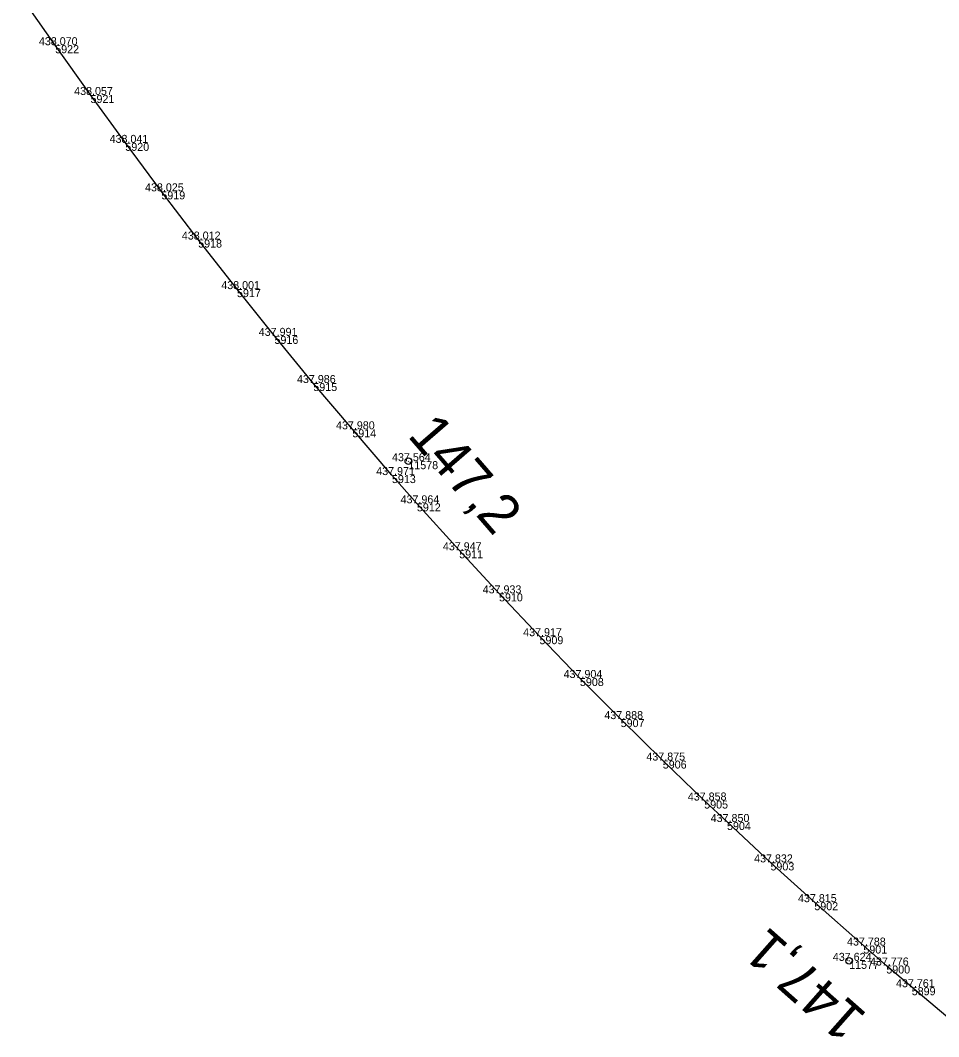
# Model space of a CAD drawing. Extents: x -654154 to -652650, y -1166925 to -1164904.
# Drawn here: x -653784.1 to -653646.5, y -1165513.2 to -1165360.8 of the extents above; entities that cross this region are included whole.
import ezdxf

# ---------------------------------------------------------------- set-up
doc = ezdxf.new("R2010")
doc.units = 0
for name, color, linetype in [('Vrstva 1', 7, 'Continuous'), ('Vrstva 60', 7, 'Continuous'), ('Vrstva 61', 7, 'Continuous'), ('Vrstva 7', 7, 'Continuous')]:
    doc.layers.add(name, color=color, linetype=linetype)

msp = doc.modelspace()

# ---------------------------------------------------------------- linework, layer by layer
at = {"layer": 'Vrstva 1'}
msp.add_lwpolyline([(-653643.5, -1165511.7), (-653650.49, -1165505.82), (-653654.3, -1165502.56), (-653657.74, -1165499.57), (-653665.09, -1165493.06), (-653671.67, -1165487.1), (-653678.18, -1165481.04), (-653681.6, -1165477.82), (-653687.81, -1165471.83), (-653694.12, -1165465.61), (-653700.23, -1165459.45), (-653706.29, -1165453.18), (-653712.36, -1165446.76), (-653718.33, -1165440.3), (-653724.67, -1165433.26), (-653728.41, -1165429.02), (-653734.35, -1165422.16), (-653740.2, -1165415.22), (-653746.02, -1165408.15), (-653751.64, -1165401.14), (-653757.46, -1165393.71), (-653762.98, -1165386.48), (-653768.38, -1165379.21), (-653773.6, -1165372.03), (-653778.89, -1165364.57), (-653784.12, -1165357.1)], dxfattribs=at)
at = {"layer": 'Vrstva 60'}
for p, q in [((-653778.89, -1165364.57), (-653778.89, -1165364.57)), ((-653773.6, -1165372.03), (-653773.6, -1165372.03)), ((-653768.38, -1165379.21), (-653768.38, -1165379.21)), ((-653762.98, -1165386.48), (-653762.98, -1165386.48)), ((-653757.46, -1165393.71), (-653757.46, -1165393.71)), ((-653751.64, -1165401.14), (-653751.64, -1165401.14)), ((-653746.02, -1165408.15), (-653746.02, -1165408.15)), ((-653740.2, -1165415.22), (-653740.2, -1165415.22)), ((-653734.35, -1165422.16), (-653734.35, -1165422.16)), ((-653725.95, -1165426.94), (-653725.95, -1165426.94)), ((-653728.41, -1165429.02), (-653728.41, -1165429.02)), ((-653724.67, -1165433.26), (-653724.67, -1165433.26)), ((-653718.33, -1165440.3), (-653718.33, -1165440.3)), ((-653712.36, -1165446.76), (-653712.36, -1165446.76)), ((-653706.29, -1165453.18), (-653706.29, -1165453.18)), ((-653700.23, -1165459.45), (-653700.23, -1165459.45)), ((-653694.12, -1165465.61), (-653694.12, -1165465.61)), ((-653687.81, -1165471.83), (-653687.81, -1165471.83)), ((-653681.6, -1165477.82), (-653681.6, -1165477.82)), ((-653678.18, -1165481.04), (-653678.18, -1165481.04)), ((-653671.67, -1165487.1), (-653671.67, -1165487.1)), ((-653665.09, -1165493.06), (-653665.09, -1165493.06)), ((-653657.74, -1165499.57), (-653657.74, -1165499.57)), ((-653659.87, -1165501.86), (-653659.87, -1165501.86)), ((-653654.3, -1165502.56), (-653654.3, -1165502.56)), ((-653650.49, -1165505.82), (-653650.49, -1165505.82))]:
    msp.add_line(p, q, dxfattribs=at)
at = {"layer": 'Vrstva 7'}
for p, q in [((-653725.98, -1165426.9), (-653725.92, -1165426.97)), ((-653659.84, -1165501.9), (-653659.91, -1165501.83))]:
    msp.add_line(p, q, dxfattribs=at)
for centre in [(-653725.95, -1165426.94), (-653659.87, -1165501.86)]:
    msp.add_circle(centre, 0.5, dxfattribs=at)

# ---------------------------------------------------------------- texts
at = {"layer": 'Vrstva 60'}
for s, p in [('5922', (-653778.89, -1165365.77)), ('5921', (-653773.6, -1165373.23)), ('5920', (-653768.38, -1165380.41)), ('5919', (-653762.98, -1165387.68)), ('5918', (-653757.46, -1165394.91)), ('5917', (-653751.64, -1165402.34)), ('5916', (-653746.02, -1165409.35)), ('5915', (-653740.2, -1165416.42)), ('5914', (-653734.35, -1165423.36)), ('11578', (-653725.95, -1165428.14)), ('5913', (-653728.41, -1165430.22)), ('5912', (-653724.67, -1165434.46)), ('5911', (-653718.33, -1165441.5)), ('5910', (-653712.36, -1165447.96)), ('5909', (-653706.29, -1165454.38)), ('5908', (-653700.23, -1165460.65)), ('5907', (-653694.12, -1165466.81)), ('5906', (-653687.81, -1165473.03)), ('5905', (-653681.6, -1165479.02)), ('5904', (-653678.18, -1165482.24)), ('5903', (-653671.67, -1165488.3)), ('5902', (-653665.09, -1165494.27)), ('5901', (-653657.74, -1165500.77)), ('11577', (-653659.87, -1165503.06)), ('5900', (-653654.3, -1165503.76)), ('5899', (-653650.49, -1165507.02))]:
    msp.add_text(s, height=1.2, dxfattribs=at).set_placement(p)
at = {"layer": 'Vrstva 61'}
for s, p in [('438.070', (-653781.34, -1165364.57)), ('438.057', (-653776.05, -1165372.03)), ('438.041', (-653770.74, -1165379.21)), ('438.025', (-653765.43, -1165386.48)), ('438.012', (-653759.91, -1165393.71)), ('438.001', (-653754, -1165401.14)), ('437.991', (-653748.38, -1165408.15)), ('437.986', (-653742.65, -1165415.22)), ('437.980', (-653736.8, -1165422.16)), ('437.564', (-653728.4, -1165426.94)), ('437.971', (-653730.77, -1165429.02)), ('437.964', (-653727.12, -1165433.26)), ('437.947', (-653720.78, -1165440.3)), ('437.933', (-653714.81, -1165446.76)), ('437.917', (-653708.74, -1165453.18)), ('437.904', (-653702.68, -1165459.45)), ('437.888', (-653696.57, -1165465.61)), ('437.875', (-653690.27, -1165471.83)), ('437.858', (-653684.06, -1165477.82)), ('437.850', (-653680.63, -1165481.04)), ('437.832', (-653674.12, -1165487.1)), ('437.815', (-653667.54, -1165493.06)), ('437.788', (-653660.19, -1165499.57)), ('437.624', (-653662.32, -1165501.86)), ('437.776', (-653656.75, -1165502.56)), ('437.761', (-653652.85, -1165505.82))]:
    msp.add_text(s, height=1.2, dxfattribs=at).set_placement(p)
at = {"layer": 'Vrstva 7'}
for s, rotation, p in [('147,2', 310.8676, (-653726.2, -1165423.14)), ('147,1', 138.4891, (-653657.01, -1165509.98))]:
    msp.add_text(s, height=6, rotation=rotation, dxfattribs=at).set_placement(p)

doc.saveas('drawing.dxf')
